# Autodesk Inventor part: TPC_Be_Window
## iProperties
Shininess: 64.0
Length Units: 11269
Angle Units: 11279
Time Units: 11290
Mass Units: 11283
Length Display Precision: 3
Angle Display Precision: 2
Compacted: True
Part Number: TPC_Be_Window
Document SubType Name: Modeling
Created: 2004-07
Project: Mucap
Material: Aluminum-6061
Description: Mucap, Beryllium Window
Designer: John Blackburn
Manufacturer: Standard
Standards Organization: Custom
Density: 0.0
Volumn: 0.0
Area: 0.0
PropertySet Name: Model Information
Control State: 0
Master: False
Checked Out: False
Title: Mucap, Be Window
Subject: Mucap
Author: John Blackburn
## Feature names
1. Extrusion1
2. Revolution1
